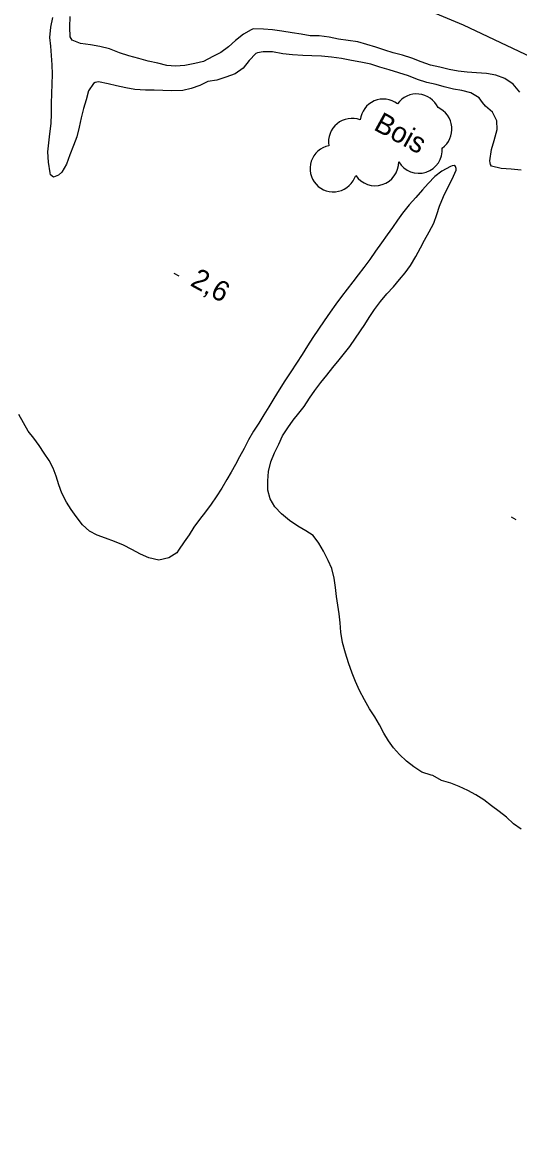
# Model space of a CAD drawing. Extents: x 219136 to 222520, y 5421589 to 5424530.
# Drawn here: x 220822.8 to 220895.9, y 5422971.4 to 5423137.9 of the extents above; entities that cross this region are included whole.
import ezdxf

# ---------------------------------------------------------------- set-up
doc = ezdxf.new("R2010")
doc.units = 0
for name, color, linetype in [('Level 2', 7, 'Continuous'), ('Level 21', 7, 'Continuous'), ('Level 3', 7, 'Continuous'), ('Level 4', 7, 'Continuous'), ('Level 44', 7, 'Continuous')]:
    doc.layers.add(name, color=color, linetype=linetype)

msp = doc.modelspace()

# ---------------------------------------------------------------- linework, layer by layer
at = {"layer": 'Level 2'}
for points in [[(220826.84, 5423121.45), (220827.04, 5423122.98), (220827.11, 5423124.42), (220827.12, 5423125.93), (220827.16, 5423127.43), (220827.18, 5423128.79), (220827.25, 5423130.28), (220827.19, 5423131.65), (220827.09, 5423133.04), (220826.99, 5423134.42), (220826.87, 5423135.7), (220827.02, 5423137.23), (220827.29, 5423138.63)], [(220896.13, 5423127.61), (220895.15, 5423128.81), (220893.91, 5423129.64), (220892.59, 5423130.14), (220891.22, 5423130.4), (220889.75, 5423130.46), (220888.36, 5423130.56), (220887.07, 5423130.7), (220885.74, 5423130.97), (220884.36, 5423131.32), (220882.95, 5423131.63), (220881.59, 5423132.1), (220880.21, 5423132.64), (220878.86, 5423133.06), (220877.48, 5423133.43), (220876.26, 5423133.82), (220874.9, 5423134.24), (220873.57, 5423134.66), (220872.28, 5423135.07), (220870.83, 5423135.25), (220869.4, 5423135.44), (220868.03, 5423135.72), (220866.57, 5423135.92), (220865.22, 5423135.95), (220863.9, 5423136.16), (220862.6, 5423136.38), (220861.06, 5423136.64), (220859.69, 5423136.84), (220858.35, 5423136.94), (220856.81, 5423136.95), (220856.53, 5423136.82), (220855.4, 5423136.2), (220854.24, 5423135.27), (220853.2, 5423134.32), (220852.04, 5423133.5), (220850.88, 5423132.87), (220849.5, 5423132.17), (220848.25, 5423131.86), (220846.75, 5423131.58), (220845.4, 5423131.44), (220844.11, 5423131.58), (220842.77, 5423131.9), (220841.35, 5423132.21), (220839.95, 5423132.57), (220838.5, 5423133), (220837.11, 5423133.43), (220835.67, 5423134), (220834.23, 5423134.34), (220832.85, 5423134.61), (220831.38, 5423134.81), (220830.13, 5423135.32), (220829.98, 5423135.52), (220829.87, 5423135.77), (220829.78, 5423137.2), (220829.87, 5423138.8)], [(220890.62, 5423126.12), (220890.14, 5423126.79), (220888.93, 5423127.51), (220887.61, 5423127.87), (220886.35, 5423128.05), (220885, 5423128.4), (220883.8, 5423128.76), (220882.44, 5423129.06), (220881.07, 5423129.5), (220879.72, 5423130.01), (220878.3, 5423130.48), (220876.86, 5423130.93), (220875.48, 5423131.32), (220874.18, 5423131.73), (220872.69, 5423132.04), (220871.31, 5423132.32), (220869.83, 5423132.6), (220868.38, 5423132.77), (220866.91, 5423132.92), (220865.5, 5423132.97), (220864.17, 5423133.03), (220862.63, 5423133.13), (220861.18, 5423133.28), (220859.66, 5423133.57), (220858.29, 5423133.56), (220857.47, 5423133.45), (220857.22, 5423133.31), (220856.22, 5423132.31), (220855.33, 5423131.16), (220854.17, 5423130.34), (220852.79, 5423129.82), (220851.47, 5423129.4), (220850.13, 5423129.19), (220848.97, 5423128.63), (220847.69, 5423128.15), (220846.45, 5423127.89), (220844.8, 5423127.82), (220843.53, 5423127.86), (220842.24, 5423127.9), (220840.97, 5423127.91), (220839.4, 5423128.02), (220838.04, 5423128.28), (220836.69, 5423128.55), (220835.47, 5423128.86), (220834.05, 5423129.14), (220833.53, 5423129.07), (220833.3, 5423128.92), (220832.55, 5423127.84), (220832.22, 5423126.5), (220831.83, 5423125.19), (220831.47, 5423123.83), (220831.16, 5423122.47), (220830.84, 5423121.01), (220830.32, 5423119.75), (220829.82, 5423118.38), (220829.29, 5423117.01), (220828.6, 5423115.8), (220828.12, 5423115.37), (220827.37, 5423115.09), (220826.97, 5423115.43), (220826.89, 5423115.73), (220826.66, 5423117.29), (220826.56, 5423118.8), (220826.69, 5423120.15), (220826.84, 5423121.45)], [(220896.35, 5423116.11), (220894.88, 5423116.24), (220893.37, 5423116.34), (220891.96, 5423116.72), (220891.81, 5423116.93), (220891.75, 5423117.2), (220891.74, 5423117.49), (220891.95, 5423119.14), (220892.37, 5423120.48), (220892.81, 5423122.09), (220892.75, 5423123.39), (220892.11, 5423124.68), (220891.07, 5423125.54), (220890.62, 5423126.12)]]:
    msp.add_lwpolyline(points, dxfattribs=at)
at = {"layer": 'Level 21'}
msp.add_lwpolyline([(220870.08, 5423145.01), (220887.78, 5423137.56), (220905.12, 5423129.34), (220919.83, 5423121.43), (220933.81, 5423114.05), (220956.41, 5423100.89), (220978.92, 5423087.62), (220998.14, 5423077.12), (221016.54, 5423066.03), (221034.15, 5423055.63), (221053.45, 5423043.85), (221075.32, 5423030.79), (221097.85, 5423018.46), (221123.32, 5423005.79), (221147.81, 5422994.15), (221173.51, 5422982.42), (221197.19, 5422971.44)], dxfattribs=at)
at = {"layer": 'Level 3'}
for p, q in [((220845.15, 5423100.89), (220845.86, 5423100.51)), ((220894.86, 5423064.95), (220895.56, 5423064.57))]:
    msp.add_line(p, q, dxfattribs=at)
at = {"layer": 'Level 4'}
for points in [[(220867.9, 5423058.52), (220867.19, 5423059.87), (220866.53, 5423061.08), (220865.68, 5423062.19), (220864.57, 5423062.9), (220863.41, 5423063.57), (220862.17, 5423064.39), (220861.02, 5423065.38), (220860.04, 5423066.43), (220859.33, 5423067.6), (220858.99, 5423068.9), (220858.99, 5423070.27), (220859.09, 5423071.64), (220859.43, 5423073.05), (220859.96, 5423074.41), (220860.59, 5423075.65), (220861.16, 5423076.89), (220861.92, 5423078.09), (220862.74, 5423079.23), (220863.57, 5423080.25), (220864.37, 5423081.23), (220865.15, 5423082.45), (220865.9, 5423083.6), (220866.8, 5423084.79), (220867.71, 5423085.88), (220868.59, 5423086.97), (220869.51, 5423088.13), (220870.3, 5423089.11), (220871.08, 5423090.09), (220871.93, 5423091.31), (220873.28, 5423093.31), (220873.95, 5423094.36), (220874.73, 5423095.57), (220875.59, 5423096.72), (220876.52, 5423097.85), (220877.51, 5423098.9), (220878.39, 5423099.96), (220879.22, 5423100.97), (220880.03, 5423102.04), (220880.83, 5423103.36), (220881.5, 5423104.64), (220882.09, 5423105.8), (220882.78, 5423107.01), (220883.47, 5423108.27), (220883.92, 5423109.59), (220884.31, 5423110.78), (220884.88, 5423112.21), (220885.49, 5423113.45), (220886.18, 5423114.8), (220886.76, 5423116.09), (220886.75, 5423116.38), (220886.66, 5423116.63), (220886.44, 5423116.79), (220886.16, 5423116.76), (220885.93, 5423116.65), (220884.66, 5423115.95), (220883.61, 5423115.16), (220882.61, 5423114.16), (220881.78, 5423113.19), (220880.81, 5423112.08), (220879.84, 5423110.98), (220878.86, 5423109.77), (220878.12, 5423108.71), (220877.37, 5423107.64), (220876.59, 5423106.55)], [(220876.59, 5423106.55), (220875.74, 5423105.38), (220874.87, 5423104.18), (220874.01, 5423102.94), (220873.15, 5423101.75), (220872.32, 5423100.64), (220871.5, 5423099.61), (220870.67, 5423098.55), (220869.86, 5423097.49), (220869.01, 5423096.35), (220868.16, 5423095.13), (220867.28, 5423093.86), (220866.44, 5423092.64), (220865.6, 5423091.42), (220864.82, 5423090.18), (220864.06, 5423088.89), (220863.24, 5423087.62), (220862.37, 5423086.33), (220861.51, 5423085.01), (220860.66, 5423083.67), (220859.88, 5423082.4), (220859.13, 5423081.17), (220858.39, 5423079.98), (220857.64, 5423078.79), (220856.9, 5423077.57), (220856.16, 5423076.3), (220855.5, 5423075.02), (220854.82, 5423073.81), (220854.21, 5423072.66), (220853.59, 5423071.55), (220852.97, 5423070.46), (220852.19, 5423069.16), (220851.36, 5423067.88), (220850.65, 5423066.8), (220849.8, 5423065.67), (220848.92, 5423064.55), (220848.09, 5423063.42), (220847.38, 5423062.31), (220846.67, 5423061.26), (220845.8, 5423060.02), (220845.55, 5423059.64)], [(220845.55, 5423059.64), (220844.4, 5423058.91), (220842.93, 5423058.54), (220841.46, 5423058.89), (220840.23, 5423059.46), (220838.94, 5423060.11), (220837.7, 5423060.78), (220836.37, 5423061.33), (220835.08, 5423061.8), (220833.83, 5423062.26), (220832.68, 5423062.81), (220831.65, 5423063.75), (220830.71, 5423064.98), (220829.99, 5423066.02), (220829.32, 5423067.09), (220828.64, 5423068.44), (220828.19, 5423069.65), (220827.8, 5423070.93), (220827.34, 5423072.14), (220826.74, 5423073.26), (220826.04, 5423074.35), (220825.27, 5423075.48), (220824.48, 5423076.54), (220823.67, 5423077.61), (220822.97, 5423078.82), (220822.28, 5423080.07)], [(220896.32, 5423018.85), (220895.23, 5423019.64), (220894.18, 5423020.62), (220893.11, 5423021.46), (220891.97, 5423022.32), (220890.84, 5423023.16), (220889.65, 5423023.91), (220888.47, 5423024.58), (220887.2, 5423025.17), (220885.99, 5423025.64), (220884.57, 5423026.06), (220883.31, 5423026.77), (220883.05, 5423026.8), (220881.67, 5423027.28), (220880.51, 5423028.06), (220879.44, 5423028.87), (220878.39, 5423029.87), (220877.53, 5423030.84), (220876.79, 5423031.89), (220876.09, 5423033.03), (220875.44, 5423034.23), (220874.77, 5423035.41), (220874, 5423036.62), (220873.24, 5423037.96), (220872.52, 5423039.32), (220871.92, 5423040.63), (220871.4, 5423041.89), (220870.86, 5423043.38), (220870.43, 5423044.83), (220870.01, 5423046.4), (220869.74, 5423047.94), (220869.64, 5423049.31), (220869.51, 5423050.61), (220869.31, 5423051.89), (220869.12, 5423053.19), (220868.98, 5423054.53), (220868.77, 5423055.91), (220868.43, 5423057.31), (220867.9, 5423058.52)]]:
    msp.add_lwpolyline(points, dxfattribs=at)
at = {"layer": 'Level 44'}
for centre, start, end in [((220880.93, 5423123.9), 24.5164, 144.5164), ((220876.04, 5423123.14), 53.2125, 173.2125), ((220882.67, 5423122.18), 305.7992, 65.7992), ((220871.4, 5423120.3), 69.6567, 189.6567), ((220868.68, 5423116.33), 101.6793, 221.6793), ((220881.26, 5423119.11), 210.6827, 4.7819), ((220874.82, 5423117.27), 213.853, 1.3011), ((220868.64, 5423116.37), 222.6554, 342.6554)]:
    msp.add_arc(centre, 3.46, start, end, dxfattribs=at)

# ---------------------------------------------------------------- texts
at = {"layer": 'Level 3'}
msp.add_text('2,6', height=3, rotation=331.383, dxfattribs=at).set_placement((220847.4, 5423099.16))
at = {"layer": 'Level 44'}
msp.add_text('Bois', height=3, rotation=331.3547, dxfattribs=at).set_placement((220874.44, 5423122.16))

doc.saveas('drawing.dxf')
